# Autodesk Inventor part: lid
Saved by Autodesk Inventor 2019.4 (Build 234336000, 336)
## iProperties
Created: 2020-02
Part Number: lid
Material: Generic
Document SubType Name: Modeling
Designer: Administrator
Density: 1 g/cm^3
Appearance: Default
Title: lid
Author: Administrator
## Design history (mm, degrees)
